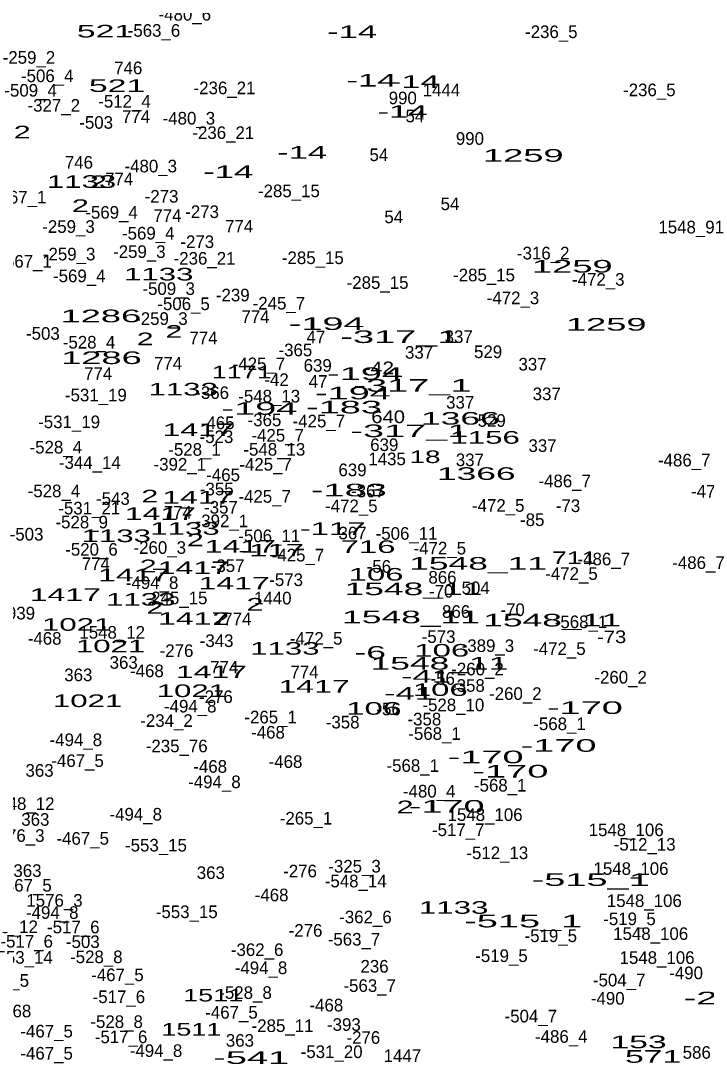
# Model space of a CAD drawing. Extents: x -660434 to -656144, y -997850 to -994016.
# Drawn here: x -658570.5 to -658353, y -995899.7 to -995568.7 of the extents above; entities that cross this region are included whole.
import ezdxf
from ezdxf.enums import TextEntityAlignment as Align

# ---------------------------------------------------------------- set-up
doc = ezdxf.new("R2010")
doc.units = 0
doc.header["$LTSCALE"] = 1.6
doc.layers.add('24', color=7, linetype='Continuous')

msp = doc.modelspace()

# ---------------------------------------------------------------- texts
at = {"layer": '24'}
for s, p in [('-480_6', (-658518.436, -995568.59)), ('-563_6', (-658528.223, -995573.7)), ('-236_5', (-658402.168, -995574.12)), ('-259_2', (-658567.888, -995582.26)), ('-506_4', (-658562.086, -995588.1)), ('746', (-658536.383, -995585.59)), ('-509_4', (-658567.366, -995592.7)), ('-236_21', (-658505.851, -995591.93)), ('990', (-658449.292, -995595.12)), ('1444', (-658437.033, -995592.61)), ('-236_5', (-658371.068, -995592.56)), ('-327_2', (-658560.008, -995597.46)), ('-512_4', (-658537.57, -995596.19)), ('774', (-658533.913, -995601.02)), ('-480_3', (-658517.151, -995601.55)), ('54', (-658445.441, -995600.86)), ('-503', (-658546.569, -995602.89)), ('-236_21', (-658506.231, -995606.13)), ('990', (-658427.982, -995607.99)), ('54', (-658456.871, -995613.15)), ('746', (-658552.033, -995615.55)), ('-480_3', (-658529.241, -995616.73)), ('774', (-658539.283, -995620.81)), ('-285_15', (-658485.415, -995624.6)), ('-567_1', (-658570.687, -995626.59)), ('-273', (-658525.821, -995626.32)), ('-569_4', (-658541.678, -995631.41)), ('-273', (-658512.951, -995631.22)), ('54', (-658434.311, -995628.71)), ('774', (-658523.953, -995632.43)), ('54', (-658452.161, -995632.84)), ('-259_3', (-658555.338, -995635.92)), ('-569_4', (-658530.038, -995638.03)), ('774', (-658501.203, -995635.79)), ('1548_91', (-658357.781, -995636.09)), ('-273', (-658514.491, -995640.73)), ('-259_3', (-658555.148, -995644.66)), ('-259_3', (-658532.868, -995643.88)), ('-316_2', (-658404.742, -995644.35)), ('-567_1', (-658568.957, -995646.95)), ('-236_21', (-658512.181, -995646)), ('-285_15', (-658477.825, -995645.82)), ('-285_15', (-658423.515, -995651.29)), ('-569_4', (-658551.928, -995651.58)), ('-285_15', (-658457.285, -995653.69)), ('-472_3', (-658387.262, -995652.69)), ('-509_3', (-658523.562, -995655.62)), ('-239', (-658503.22, -995657.65)), ('-506_5', (-658518.832, -995660.43)), ('-245_7', (-658488.582, -995660.24)), ('-472_3', (-658414.332, -995658.55)), ('774', (-658496.023, -995664.54)), ('-259_3', (-658525.868, -995665.12)), ('-503', (-658563.469, -995669.83)), ('47', (-658476.847, -995670.95)), ('337', (-658431.553, -995670.85)), ('-528_4', (-658548.817, -995672.62)), ('774', (-658512.533, -995671.26)), ('-365', (-658483.37, -995675.07)), ('337', (-658444.123, -995675.84)), ('529', (-658422.223, -995675.65)), ('774', (-658523.763, -995679.33)), ('-425_7', (-658494.922, -995679.48)), ('639', (-658476.278, -995679.98)), ('337', (-658408.123, -995679.59)), ('774', (-658545.913, -995682.57)), ('-42', (-658489.339, -995684.5)), ('47', (-658476.177, -995685.07)), ('-531_19', (-658546.655, -995689.38)), ('-366', (-658509.775, -995688.62)), ('-548_13', (-658491.669, -995689.73)), ('337', (-658403.613, -995689)), ('337', (-658431.073, -995691.69)), ('-365', (-658493.17, -995697.26)), ('-425_7', (-658475.912, -995697.64)), ('529', (-658421.073, -995697.45)), ('-531_19', (-658555.145, -995697.88)), ('-465', (-658508.015, -995698.18)), ('-523', (-658508.395, -995702.6)), ('-425_7', (-658488.972, -995702.15)), ('-528_4', (-658559.377, -995705.92)), ('-528_1', (-658515.356, -995706.64)), ('-548_13', (-658490.039, -995706.61)), ('639', (-658455.158, -995705.14)), ('337', (-658404.953, -995705.42)), ('-344_14', (-658548.568, -995710.8)), ('1435', (-658454.274, -995709.64)), ('337', (-658428.003, -995709.93)), ('-486_7', (-658359.988, -995710.01)), ('-392_1', (-658520.022, -995711.34)), ('-425_7', (-658492.812, -995711.37)), ('639', (-658465.238, -995713.12)), ('-465', (-658506.295, -995714.69)), ('-486_7', (-658397.908, -995716.63)), ('-528_4', (-658559.957, -995719.8)), ('-355', (-658508.315, -995719.2)), ('-367', (-658460.345, -995719.82)), ('-472_6', (-658349.498, -995719.92)), ('-543', (-658541.249, -995722.21)), ('-425_7', (-658493.102, -995721.54)), ('-531_21', (-658548.759, -995725.26)), ('774', (-658520.693, -995726.55)), ('-357', (-658506.981, -995724.99)), ('-472_5', (-658465.622, -995724.54)), ('-472_5', (-658419.002, -995724.41)), ('-73', (-658396.861, -995724.5)), ('-528_9', (-658551.148, -995729.67)), ('-392_1', (-658506.682, -995729.3)), ('-85', (-658408.215, -995728.93)), ('-503', (-658568.659, -995733.53)), ('-506_11', (-658491.659, -995734.05)), ('-367', (-658466.115, -995733.15)), ('-506_11', (-658448.079, -995733.28)), ('-520_6', (-658548.052, -995738.34)), ('-260_3', (-658526.382, -995737.76)), ('-425_7', (-658482.542, -995740.16)), ('-472_5', (-658437.532, -995737.95)), ('774', (-658546.683, -995742.91)), ('-357', (-658504.861, -995743.52)), ('-56', (-658456.88, -995743.75)), ('-486_7', (-658385.518, -995741.4)), ('-486_7', (-658355.468, -995742.56)), ('866', (-658436.688, -995747.21)), ('-472_5', (-658395.762, -995746.02)), ('-494_8', (-658528.816, -995748.91)), ('-573', (-658486.301, -995747.97)), ('504', (-658426.165, -995750.55)), ('-245_15', (-658521.089, -995753.75)), ('1440', (-658490.532, -995753.81)), ('-70', (-658437.094, -995751.63)), ('939', (-658570.418, -995758.57)), ('774', (-658501.773, -995760.4)), ('866', (-658432.368, -995758.06)), ('-70', (-658414.444, -995757.5)), ('-568_1', (-658392.742, -995761.33)), ('-468', (-658562.905, -995766.58)), ('1548_12', (-658541.476, -995764.66)), ('-472_5', (-658476.752, -995766.57)), ('-573', (-658437.921, -995766.03)), ('-276', (-658521.065, -995770.47)), ('-343', (-658508.359, -995767.32)), ('-389_3', (-658422.278, -995768.89)), ('-472_5', (-658399.602, -995769.84)), ('363', (-658537.833, -995774.22)), ('-468', (-658530.465, -995776.88)), ('774', (-658505.923, -995775.72)), ('-260_2', (-658425.582, -995776.31)), ('363', (-658552.233, -995778.16)), ('774', (-658480.483, -995777.26)), ('-56', (-658436.62, -995779.29)), ('-260_2', (-658380.172, -995778.91)), ('-358', (-658428.615, -995781.53)), ('-276', (-658508.575, -995785.08)), ('-260_2', (-658413.582, -995784.1)), ('-494_8', (-658516.716, -995788.09)), ('-494_8', (-658516.716, -995788.09)), ('-56', (-658453.81, -995788.99)), ('-528_10', (-658433.239, -995787.69)), ('-234_2', (-658524.247, -995792.65)), ('-265_1', (-658491.212, -995791.55)), ('-358', (-658468.355, -995793.15)), ('-358', (-658442.435, -995792.19)), ('-568_1', (-658399.562, -995793.68)), ('-468', (-658492.055, -995796.37)), ('-568_1', (-658439.212, -995796.77)), ('-494_8', (-658553.006, -995798.75)), ('-235_76', (-658521.013, -995800.72)), ('-467_5', (-658552.468, -995805.38)), ('-468', (-658486.495, -995805.68)), ('-568_1', (-658446.122, -995806.93)), ('363', (-658564.523, -995808.47)), ('-468', (-658510.395, -995807.2)), ('-494_8', (-658509.046, -995812.09)), ('-568_1', (-658418.382, -995813.17)), ('-480_4', (-658440.905, -995815.05)), ('1548_12', (-658570.186, -995819.02)), ('-494_8', (-658534.006, -995822.37)), ('1548_106', (-658423.175, -995822.5)), ('363', (-658565.863, -995824.03)), ('-265_1', (-658479.982, -995823.63)), ('1576_3', (-658571.88, -995829.14)), ('-467_5', (-658550.838, -995830.04)), ('-517_7', (-658431.697, -995827.31)), ('1548_106', (-658378.415, -995827.32)), ('-553_15', (-658527.595, -995832.19)), ('-512_13', (-658372.549, -995831.92)), ('-512_13', (-658419.299, -995834.61)), ('-325_3', (-658464.592, -995838.86)), ('1548_106', (-658376.875, -995839.62)), ('363', (-658568.363, -995840.26)), ('363', (-658510.183, -995840.92)), ('-276', (-658481.885, -995840.39)), ('-467_5', (-658568.988, -995844.93)), ('-548_14', (-658464.214, -995843.57)), ('1576_3', (-658559.79, -995849.69)), ('-468', (-658490.905, -995847.99)), ('1548_106', (-658372.655, -995849.8)), ('-553_15', (-658517.825, -995853.32)), ('-494_8', (-658560.506, -995853.57)), ('-362_6', (-658461.133, -995854.97)), ('-519_5', (-658377.362, -995855.56)), ('1548_12', (-658575.456, -995858.07)), ('-517_6', (-658553.817, -995858.16)), ('-276', (-658480.135, -995859.22)), ('-517_6', (-658568.607, -995862.67)), ('-503', (-658550.799, -995862.81)), ('-563_7', (-658464.764, -995862.04)), ('-519_5', (-658402.322, -995860.93)), ('1548_106', (-658370.635, -995860.26)), ('-362_6', (-658495.503, -995865.35)), ('-553_14', (-658570.149, -995867.79)), ('-528_8', (-658546.512, -995867.62)), ('-519_5', (-658417.972, -995867.26)), ('1548_106', (-658368.615, -995867.85)), ('-494_8', (-658494.266, -995871.08)), ('236', (-658458.243, -995870.61)), ('-490', (-658359.399, -995872.71)), ('-467_5', (-658576.198, -995875.11)), ('-467_5', (-658539.818, -995873.32)), ('-504_7', (-658380.636, -995874.99)), ('-528_8', (-658499.172, -995878.96)), ('-563_7', (-658459.774, -995876.74)), ('-517_6', (-658539.367, -995880.29)), ('-468', (-658473.535, -995882.93)), ('-490', (-658384.269, -995880.78)), ('-468', (-658572.505, -995884.8)), ('-467_5', (-658503.628, -995885.23)), ('-504_7', (-658408.666, -995886.42)), ('-528_8', (-658540.072, -995888.18)), ('-285_11', (-658487.429, -995889.46)), ('-393', (-658467.97, -995889.09)), ('-467_5', (-658562.288, -995891.19)), ('-517_6', (-658538.657, -995893)), ('-486_4', (-658399.006, -995892.88)), ('363', (-658500.963, -995894.12)), ('-276', (-658461.795, -995893.21)), ('-467_5', (-658562.288, -995898.2)), ('-494_8', (-658527.576, -995897.38)), ('-531_20', (-658471.859, -995897.73)), ('1447', (-658449.424, -995899)), ('586', (-658356.013, -995897.94))]:
    msp.add_text(s, height=4, dxfattribs=at).set_placement(p, align=Align.CENTER)
for s, width, p in [('521', 2, (-658543.777, -995573.93)), ('-14', 2.05, (-658465.346, -995574.12)), ('521', 2, (-658539.937, -995591.22)), ('-14', 2.05, (-658459.196, -995589.49)), ('-14', 2.05, (-658445.516, -995589.93)), ('-14', 2.05, (-658449.356, -995599.42)), ('2', 1.8, (-658570.021, -995605.94)), ('-14', 2.05, (-658481.226, -995612.39)), ('1259', 2.15, (-658411.053, -995613.36)), ('1133', 1.85, (-658551.204, -995621.64)), ('-14', 2.05, (-658504.656, -995618.53)), ('2', 1.8, (-658545.831, -995621.69)), ('2', 1.8, (-658551.571, -995629.3)), ('1133', 1.85, (-658526.724, -995651.03)), ('1259', 2.15, (-658395.503, -995648.52)), ('1286', 2.15, (-658545.083, -995664.28)), ('-194', 2.25, (-658473.451, -995666.74)), ('1259', 2.15, (-658384.743, -995666.95)), ('2', 1.8, (-658521.921, -995669.2)), ('-317_1', 2.25, (-658450.353, -995670.87)), ('2', 1.8, (-658531.031, -995671.56)), ('1286', 2.15, (-658544.893, -995677.54)), ('-42', 1.25, (-658456.88, -995680.76)), ('1171', 1.6, (-658500.365, -995682.1)), ('-194', 2.25, (-658461.261, -995682.59)), ('1133', 1.85, (-658518.954, -995687.52)), ('-317_1', 2.25, (-658446.223, -995686.33)), ('-194', 2.25, (-658465.101, -995688.74)), ('-194', 2.25, (-658494.771, -995693.64)), ('-183', 2.25, (-658467.931, -995693.2)), ('640', 1.2, (-658453.94, -995696.28)), ('1366', 2.1, (-658431.017, -995696.77)), ('1417', 1.9, (-658514.205, -995700.4)), ('-317_1', 2.25, (-658447.183, -995700.73)), ('1156', 1.85, (-658423.159, -995702.82)), ('18', 1.65, (-658442.237, -995708.95)), ('1366', 2.1, (-658425.977, -995714.3)), ('-183', 2.25, (-658466.401, -995719.51)), ('2', 1.8, (-658529.551, -995721.45)), ('1417', 1.9, (-658514.305, -995721.81)), ('1417', 1.9, (-658526.195, -995726.99)), ('1133', 1.85, (-658540.174, -995734.03)), ('1133', 1.85, (-658518.394, -995731.72)), ('-117', 1.95, (-658471.551, -995731.77)), ('2', 1.8, (-658515.111, -995735.33)), ('1417', 1.9, (-658500.845, -995737.36)), ('716', 1.95, (-658460.317, -995737.48)), ('-117', 1.95, (-658491.041, -995738.59)), ('2', 1.8, (-658530.071, -995743.59)), ('1548_11', 2.1, (-658425.397, -995742.79)), ('711', 1.6, (-658394.859, -995741.01)), ('1417', 1.9, (-658534.655, -995746.47)), ('1417', 1.9, (-658515.725, -995744.18)), ('106', 1.95, (-658457.759, -995746.25)), ('1417', 1.9, (-658502.785, -995749.07)), ('1417', 1.9, (-658556.335, -995752.71)), ('1548_11', 2.1, (-658445.907, -995750.86)), ('1133', 1.85, (-658532.404, -995754.19)), ('2', 1.8, (-658527.961, -995756.79)), ('2', 1.8, (-658496.181, -995755.76)), ('1417', 1.9, (-658515.655, -995760.28)), ('2', 1.8, (-658507.031, -995760.34)), ('1548_11', 2.1, (-658446.677, -995759.79)), ('1021', 1.85, (-658552.74, -995762.17)), ('1548_11', 2.1, (-658401.927, -995760.79)), ('-73', 1.2, (-658383.02, -995766.08)), ('1021', 1.85, (-658541.99, -995768.99)), ('1133', 1.85, (-658486.704, -995769.75)), ('106', 1.95, (-658436.929, -995770.36)), ('-6', 2.1, (-658459.619, -995771.03)), ('1548_11', 2.1, (-658437.657, -995774.49)), ('1417', 1.9, (-658509.985, -995777.19)), ('-41', 2.05, (-658441.926, -995778.62)), ('1021', 1.85, (-658516.36, -995783.2)), ('1417', 1.9, (-658477.435, -995781.8)), ('106', 1.95, (-658437.399, -995782.85)), ('1021', 1.85, (-658549.29, -995786.37)), ('-41', 2.05, (-658447.296, -995784)), ('106', 1.95, (-658458.529, -995788.8)), ('-170', 2.25, (-658391.511, -995788.56)), ('-170', 2.25, (-658399.861, -995800.55)), ('-170', 2.25, (-658423.001, -995804.2)), ('-170', 2.25, (-658415.131, -995808.72)), ('2', 1.8, (-658448.561, -995820.05)), ('-170', 2.25, (-658435.381, -995819.87)), ('-515_1', 2.25, (-658389.667, -995843.11)), ('1133', 1.85, (-658433.144, -995851.96)), ('-515_1', 2.25, (-658411.077, -995856.27)), ('1511', 1.6, (-658509.45, -995879.78)), ('-221', 2.25, (-658348.151, -995880.7)), ('1511', 1.6, (-658516.36, -995890.62)), ('153', 2, (-658374.487, -995894.61)), ('-541', 2.25, (-658497.396, -995899.6)), ('571', 2, (-658369.863, -995899.22))]:
    msp.add_text(s, height=4, dxfattribs=dict(at, width=width)).set_placement(p, align=Align.CENTER)

doc.saveas('drawing.dxf')
